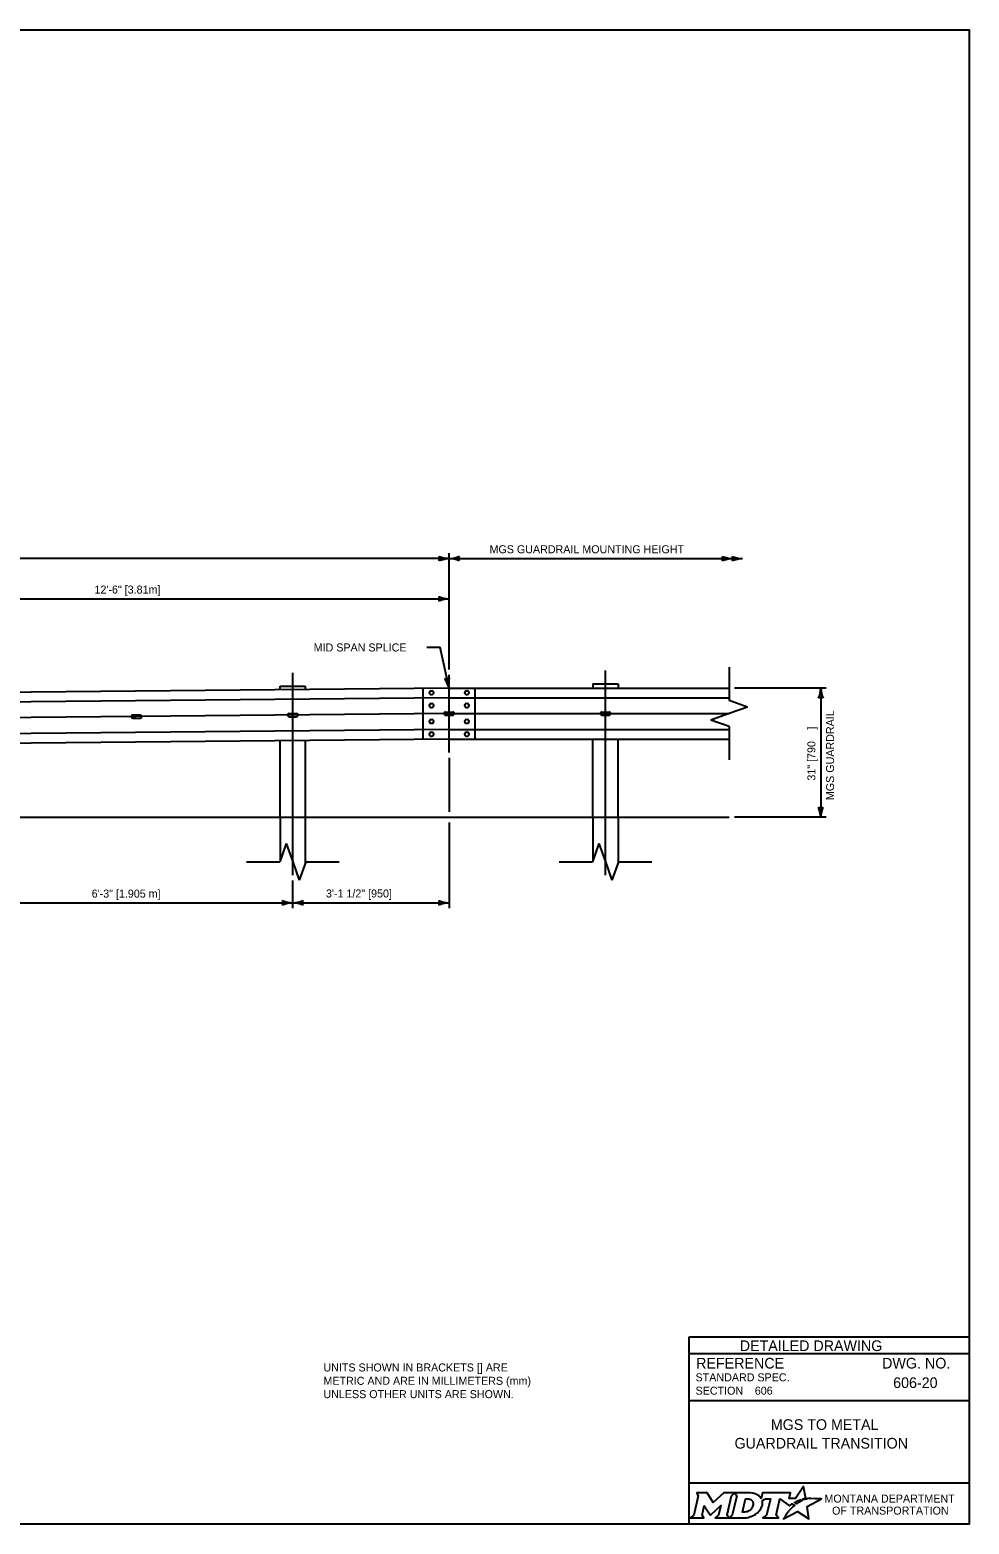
# Model space of a CAD drawing. Extents: x 49991.4 to 50070, y 49987.6 to 50011.4.
# Drawn here: x 50009.71 to 50016.75, y 49987.8 to 49999 of the extents above; entities that cross this region are included whole.
import ezdxf

# ---------------------------------------------------------------- set-up
doc = ezdxf.new("R2010")
doc.units = 0
for name, color, linetype in [('Default', 7, 'Continuous'), ('Level 1', 7, 'Continuous'), ('Level 2', 7, 'Continuous'), ('Level 3', 7, 'Continuous'), ('Level 4', 7, 'Continuous'), ('Level 5', 7, 'Continuous'), ('Level 6', 7, 'Continuous')]:
    doc.layers.add(name, color=color, linetype=linetype)

msp = doc.modelspace()

# ---------------------------------------------------------------- linework, layer by layer
at = {"layer": 'Default'}
for points in [[(50015.513, 49987.981), (50015.502, 49987.987), (50015.514, 49987.99), (50015.526, 49987.991), (50015.508, 49988.082), (50015.449, 49987.99), (50015.401, 49987.99), (50015.412, 49988.034), (50015.202, 49988.034), (50015.192, 49987.991), (50015.186, 49988)], [(50014.706, 49988.034), (50014.72, 49988.01), (50014.686, 49987.867), (50014.66, 49987.845), (50014.762, 49987.845), (50014.749, 49987.867), (50014.765, 49987.937), (50014.809, 49987.868), (50014.814, 49987.868), (50014.889, 49987.938), (50014.872, 49987.867), (50014.848, 49987.845), (50014.949, 49987.845), (50014.936, 49987.868), (50014.969, 49988.011)], [(50014.969, 49988.011), (50014.994, 49988.034), (50014.912, 49988.034), (50014.832, 49987.961), (50014.788, 49988.034), (50014.706, 49988.034)], [(50015.108, 49988.034), (50014.994, 49988.034), (50015.009, 49988.011), (50014.975, 49987.867), (50014.949, 49987.845), (50015.06, 49987.845)], [(50015.132, 49987.947), (50015.13, 49987.939), (50015.127, 49987.93), (50015.123, 49987.922), (50015.118, 49987.914), (50015.111, 49987.907), (50015.103, 49987.901), (50015.095, 49987.896), (50015.086, 49987.892), (50015.077, 49987.89), (50015.067, 49987.889), (50015.052, 49987.889), (50015.075, 49987.989), (50015.091, 49987.989), (50015.099, 49987.988), (50015.106, 49987.986), (50015.113, 49987.983), (50015.119, 49987.979), (50015.124, 49987.974), (50015.128, 49987.968), (50015.13, 49987.962), (50015.132, 49987.955), (50015.132, 49987.952), (50015.132, 49987.947)], [(50015.199, 49987.975), (50015.224, 49987.988), (50015.261, 49987.988), (50015.232, 49987.867), (50015.205, 49987.845), (50015.321, 49987.845), (50015.304, 49987.867), (50015.332, 49987.988), (50015.403, 49987.936), (50015.424, 49987.951), (50015.444, 49987.94)], [(50015.388, 49987.884), (50015.373, 49987.86), (50015.368, 49987.852), (50015.362, 49987.844), (50015.36, 49987.839), (50015.465, 49987.893), (50015.549, 49987.838), (50015.536, 49987.93), (50015.643, 49987.989), (50015.594, 49987.989), (50015.564, 49987.99), (50015.543, 49987.99), (50015.536, 49987.989), (50015.531, 49987.987), (50015.523, 49987.985), (50015.513, 49987.981)], [(50015.462, 49987.954), (50015.46, 49987.952), (50015.442, 49987.961), (50015.452, 49987.967), (50015.456, 49987.969), (50015.465, 49987.973), (50015.47, 49987.976), (50015.478, 49987.979), (50015.485, 49987.982), (50015.497, 49987.974), (50015.493, 49987.972), (50015.489, 49987.97), (50015.484, 49987.967), (50015.479, 49987.965), (50015.478, 49987.963), (50015.475, 49987.962), (50015.472, 49987.96), (50015.47, 49987.959), (50015.467, 49987.957), (50015.465, 49987.955), (50015.462, 49987.954)], [(50015.106, 49987.852), (50015.114, 49987.855), (50015.127, 49987.86), (50015.148, 49987.871)], [(50015.402, 49987.9), (50015.402, 49987.9)]]:
    msp.add_lwpolyline(points, dxfattribs=at)
for centre, radius, start, end in [((50015.131, 49987.955), 0.0709, 339.5329, 15.8582), ((50015.087, 49987.973), 0.118, 300.9103, 339.1383)]:
    msp.add_arc(centre, radius, start, end, dxfattribs=at)
for centre, major_axis, ratio, start_param, end_param in [((50015.106, 49987.986), (0.0834, -0.0037), 0.568097, 0.61298, 1.570796), ((50015.161, 49987.994), (0.0361, -0.0295), 0.469099, 1.225588, 1.570796), ((50015.06, 49987.993), (0, 0.148), 0.987302, 3.139398, 3.456847), ((50015.395, 49987.892), (-0.00694, -0.00806), 0.008222, 0, 3.137361), ((50015.412, 49987.911), (-0.0098, -0.0102), 0.016458, 3.141593, 6.279097), ((50015.433, 49987.93), (-0.0112, -0.0097), 0.021651, 3.157348, 6.283185)]:
    msp.add_ellipse(centre, major_axis=major_axis, ratio=ratio, start_param=start_param, end_param=end_param, dxfattribs=at)
at = {"layer": 'Level 1'}
for p, q in [((50012.853, 49994.066), (50002.306, 49993.964)), ((50012.853, 49993.993), (50002.306, 49993.892)), ((50011.587, 49994.054), (50011.587, 49994.081)), ((50011.587, 49994.081), (50011.775, 49994.081)), ((50011.775, 49994.081), (50011.775, 49994.055)), ((50012.658, 49993.681), (50012.658, 49994.064)), ((50012.717, 49994.045), (50012.724, 49994.045)), ((50012.717, 49994.017), (50012.724, 49994.017)), ((50012.853, 49994.066), (50014.951, 49994.066)), ((50012.853, 49993.993), (50014.951, 49993.993)), ((50012.982, 49994.045), (50012.989, 49994.045)), ((50012.982, 49994.017), (50012.989, 49994.017)), ((50013.931, 49994.097), (50014.119, 49994.097)), ((50013.931, 49994.097), (50013.931, 49994.066)), ((50014.119, 49994.097), (50014.119, 49994.066)), ((50012.717, 49993.949), (50012.724, 49993.949)), ((50012.717, 49993.921), (50012.724, 49993.921)), ((50012.826, 49993.886), (50012.88, 49993.886)), ((50012.982, 49993.949), (50012.989, 49993.949)), ((50012.982, 49993.921), (50012.989, 49993.921)), ((50013.998, 49993.886), (50014.052, 49993.886)), ((50010.482, 49993.864), (50010.537, 49993.864)), ((50010.482, 49993.84), (50010.537, 49993.84)), ((50011.654, 49993.874), (50011.709, 49993.874)), ((50011.654, 49993.851), (50011.709, 49993.851)), ((50012.717, 49993.83), (50012.724, 49993.83)), ((50012.717, 49993.802), (50012.724, 49993.802)), ((50012.826, 49993.863), (50012.88, 49993.863)), ((50012.982, 49993.83), (50012.989, 49993.83)), ((50012.982, 49993.802), (50012.989, 49993.802)), ((50013.998, 49993.863), (50014.052, 49993.863)), ((50012.853, 49993.755), (50002.306, 49993.654)), ((50012.853, 49993.683), (50002.306, 49993.581)), ((50011.587, 49993.097), (50011.587, 49993.671)), ((50011.775, 49993.673), (50011.775, 49993.097)), ((50012.717, 49993.734), (50012.724, 49993.734)), ((50012.717, 49993.706), (50012.724, 49993.706)), ((50012.853, 49993.755), (50014.951, 49993.755)), ((50012.853, 49993.683), (50014.951, 49993.683)), ((50012.982, 49993.734), (50012.989, 49993.734)), ((50012.982, 49993.706), (50012.989, 49993.706)), ((50013.931, 49993.097), (50013.931, 49993.683)), ((50014.119, 49993.097), (50014.119, 49993.683)), ((50001.202, 49993.097), (50014.951, 49993.097))]:
    msp.add_line(p, q, dxfattribs=at)
msp.add_lwpolyline([(49999.384, 49998.999), (50016.75, 49998.999), (50016.75, 49987.799), (49999.384, 49987.799)], close=True, dxfattribs=at)
for centre, major_axis, start_param, end_param in [((50012.717, 49994.031), (-0.0142, 0), 4.712389, 7.853982), ((50012.724, 49994.031), (-0.0142, 0), 1.570796, 4.712389), ((50012.982, 49994.031), (-0.0142, 0), 4.712389, 7.853982), ((50012.989, 49994.031), (-0.0142, 0), 1.570796, 4.712389), ((50012.717, 49993.935), (-0.0142, 0), 4.712389, 7.853982), ((50012.724, 49993.935), (-0.0142, 0), 1.570796, 4.712389), ((50012.826, 49993.875), (-0.0117, 0), 4.712389, 7.853982), ((50012.88, 49993.875), (-0.0117, 0), 1.570796, 4.712389), ((50012.982, 49993.935), (-0.0142, 0), 4.712389, 7.853982), ((50012.989, 49993.935), (-0.0142, 0), 1.570796, 4.712389), ((50013.998, 49993.875), (-0.0117, 0), 4.712389, 7.853982), ((50014.052, 49993.875), (-0.0117, 0), 1.570796, 4.712389), ((50010.482, 49993.852), (-0.0117, 0), 4.712389, 7.853982), ((50010.537, 49993.852), (-0.0117, 0), 1.570796, 4.712389), ((50011.654, 49993.863), (-0.0117, 0), 4.712389, 7.853982), ((50011.709, 49993.863), (-0.0117, 0), 1.570796, 4.712389), ((50012.717, 49993.816), (-0.0142, 0), 4.712389, 7.853982), ((50012.724, 49993.816), (-0.0142, 0), 1.570796, 4.712389), ((50012.982, 49993.816), (-0.0142, 0), 4.712389, 7.853982), ((50012.989, 49993.816), (-0.0142, 0), 1.570796, 4.712389), ((50012.717, 49993.72), (-0.0142, 0), 4.712389, 7.853982), ((50012.724, 49993.72), (-0.0142, 0), 1.570796, 4.712389), ((50012.982, 49993.72), (-0.0142, 0), 4.712389, 7.853982), ((50012.989, 49993.72), (-0.0142, 0), 1.570796, 4.712389)]:
    msp.add_ellipse(centre, major_axis=major_axis, ratio=0.998676, start_param=start_param, end_param=end_param, dxfattribs=at)
at = {"layer": 'Level 3'}
for p, q in [((50012.853, 49995.036), (50002.306, 49995.036)), ((50012.853, 49994.206), (50012.853, 49995.076)), ((50012.853, 49995.036), (50015.05, 49995.036)), ((50008.166, 49994.734), (50012.853, 49994.734)), ((50015.678, 49994.066), (50014.991, 49994.066)), ((50015.638, 49994.066), (50015.638, 49993.097)), ((50012.853, 49993.543), (50012.853, 49993.137)), ((50012.853, 49993.057), (50012.853, 49992.416)), ((50015.678, 49993.097), (50014.991, 49993.097)), ((50011.681, 49992.416), (50011.681, 49992.623)), ((50009.337, 49992.456), (50011.681, 49992.456)), ((50011.681, 49992.456), (50012.853, 49992.456))]:
    msp.add_line(p, q, dxfattribs=at)
msp.add_lwpolyline([(50012.853, 49994.066), (50012.785, 49994.37), (50012.685, 49994.37)], dxfattribs=at)
for centre, radius, start, end in [((50012.862, 49995.258), 0.222, 247.456, 267.6395), ((50012.725, 49995.036), 0.0548, 342.1388, 17.8612), ((50012.865, 49994.803), 0.233, 92.8273, 112.0772), ((50012.842, 49995.269), 0.233, 272.8273, 292.0772), ((50012.844, 49994.814), 0.222, 67.456, 87.6395), ((50012.981, 49995.036), 0.0548, 162.1388, 197.8612), ((50014.986, 49995.258), 0.222, 247.456, 267.6395), ((50014.848, 49995.036), 0.0548, 342.1388, 17.8612), ((50014.988, 49994.803), 0.233, 92.8273, 112.0772), ((50015.059, 49995.258), 0.222, 247.456, 267.6395), ((50014.922, 49995.036), 0.0548, 342.1388, 17.8612), ((50015.062, 49994.803), 0.233, 92.8273, 112.0772), ((50012.862, 49994.957), 0.222, 247.456, 267.6395), ((50012.725, 49994.734), 0.0548, 342.1388, 17.8612), ((50012.865, 49994.502), 0.233, 92.8273, 112.0772), ((50012.825, 49994.191), 0.0548, 264.6827, 300.405), ((50012.628, 49994.004), 0.233, 15.3711, 34.621), ((50013.072, 49994.105), 0.222, 169.9998, 190.1834), ((50015.416, 49994.075), 0.222, 337.4599, 357.6434), ((50015.871, 49994.077), 0.233, 182.8312, 202.0811), ((50015.638, 49993.938), 0.0548, 72.1427, 107.8651), ((50015.638, 49993.225), 0.0548, 252.1388, 287.8612), ((50015.405, 49993.086), 0.233, 2.8273, 22.0772), ((50015.86, 49993.088), 0.222, 157.456, 177.6395), ((50011.69, 49992.678), 0.222, 247.456, 267.6395), ((50011.553, 49992.456), 0.0548, 342.1388, 17.8612), ((50011.693, 49992.223), 0.233, 92.8273, 112.0772), ((50011.67, 49992.688), 0.233, 272.8273, 292.0772), ((50011.672, 49992.234), 0.222, 67.456, 87.6395), ((50011.809, 49992.456), 0.0548, 162.1388, 197.8612), ((50012.862, 49992.678), 0.222, 247.456, 267.6395), ((50012.725, 49992.456), 0.0548, 342.1388, 17.8612), ((50012.865, 49992.223), 0.233, 92.8273, 112.0772)]:
    msp.add_arc(centre, radius, start, end, dxfattribs=at)
at = {"layer": 'Level 4'}
for p, q in [((50013.048, 49993.683), (50013.048, 49994.066)), ((50011.587, 49993.097), (50011.587, 49992.773)), ((50011.775, 49993.097), (50011.775, 49992.753)), ((50013.931, 49993.097), (50013.931, 49992.773)), ((50014.119, 49993.097), (50014.119, 49992.753))]:
    msp.add_line(p, q, dxfattribs=at)
at = {"layer": 'Level 5'}
for p, q in [((50011.681, 49992.663), (50011.681, 49994.181)), ((50012.853, 49993.583), (50012.853, 49994.166)), ((50014.025, 49992.663), (50014.025, 49994.197)), ((50012.853, 49993.874), (50002.306, 49993.773)), ((50012.853, 49993.874), (50014.951, 49993.874)), ((50016.75, 49989.199), (50014.65, 49989.199)), ((50014.65, 49989.199), (50014.65, 49987.799)), ((50016.75, 49989.074), (50014.65, 49989.074)), ((50016.386, 49988.859), (50016.386, 49988.859)), ((50015.144, 49988.799), (50015.144, 49988.799)), ((50016.75, 49988.724), (50014.65, 49988.724)), ((50015.7, 49988.475), (50015.7, 49988.475)), ((50016.75, 49988.106), (50014.65, 49988.106))]:
    msp.add_line(p, q, dxfattribs=at)
at = {"layer": 'Level 6'}
for p, q in [((50014.951, 49994.222), (50014.951, 49993.972)), ((50015.089, 49993.923), (50014.951, 49993.972)), ((50015.089, 49993.923), (50014.951, 49993.874)), ((50014.951, 49993.874), (50014.814, 49993.826)), ((50014.951, 49993.777), (50014.814, 49993.826)), ((50014.951, 49993.777), (50014.951, 49993.527)), ((50011.632, 49992.9), (50011.584, 49992.763)), ((50011.632, 49992.9), (50011.681, 49992.763)), ((50013.976, 49992.9), (50013.928, 49992.763)), ((50013.976, 49992.9), (50014.025, 49992.763)), ((50011.334, 49992.763), (50011.584, 49992.763)), ((50011.681, 49992.763), (50011.73, 49992.626)), ((50011.778, 49992.763), (50011.73, 49992.626)), ((50011.778, 49992.763), (50012.028, 49992.763)), ((50013.678, 49992.763), (50013.928, 49992.763)), ((50014.025, 49992.763), (50014.073, 49992.626)), ((50014.122, 49992.763), (50014.073, 49992.626)), ((50014.122, 49992.763), (50014.372, 49992.763))]:
    msp.add_line(p, q, dxfattribs=at)

# ---------------------------------------------------------------- texts
at = {"layer": 'Default'}
for s, p in [('MONTANA DEPARTMENT', (50015.666, 49987.96)), ('OF TRANSPORTATION', (50015.723, 49987.87))]:
    msp.add_text(s, height=0.06, dxfattribs=at).set_placement(p)
at = {"layer": 'Level 2'}
for s, height, p in [('MGS GUARDRAIL MOUNTING HEIGHT', 0.06, (50013.156, 49995.076)), ('12\'-6" [3.81m]', 0.06, (50010.195, 49994.774)), ('MID SPAN SPLICE', 0.06, (50011.838, 49994.34)), ('6\'-3" [1.905 m]', 0.06, (50010.174, 49992.495)), ('3\'-1 1/2" [950]', 0.06, (50011.93, 49992.496)), ('UNITS SHOWN IN BRACKETS [] ARE ', 0.06, (50011.911, 49988.943)), ('METRIC AND ARE IN MILLIMETERS (mm) ', 0.06, (50011.911, 49988.843)), ('606-20', 0.0799, (50016.181, 49988.819)), ('UNLESS OTHER UNITS ARE SHOWN.', 0.06, (50011.911, 49988.743)), ('606', 0.06, (50015.144, 49988.769)), ('MGS TO METAL', 0.0799, (50015.264, 49988.505)), ('GUARDRAIL TRANSITION', 0.0799, (50014.992, 49988.365))]:
    msp.add_text(s, height=height, dxfattribs=at).set_placement(p)
for s, p in [('MGS GUARDRAIL', (50015.738, 49993.226)), (']', (50015.598, 49993.754)), ('31" [790', (50015.598, 49993.372))]:
    msp.add_text(s, height=0.06, rotation=90, dxfattribs=at).set_placement(p)
at = {"layer": 'Level 5'}
for s, height, p in [('DETAILED DRAWING', 0.0799, (50015.031, 49989.096)), ('REFERENCE', 0.08, (50014.704, 49988.965)), ('DWG. NO.', 0.08, (50016.098, 49988.965)), ('STANDARD SPEC.', 0.06, (50014.7, 49988.869)), ('SECTION', 0.06, (50014.7, 49988.769))]:
    msp.add_text(s, height=height, dxfattribs=at).set_placement(p)

doc.saveas('drawing.dxf')
